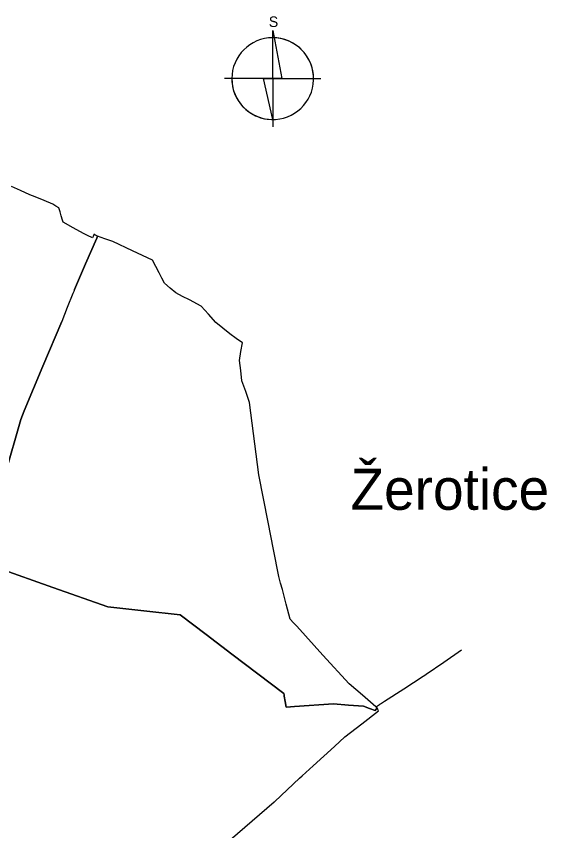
# Model space of a CAD drawing. Extents: x -637420 to -632365, y -1190340 to -1186955.
# Drawn here: x -633244 to -632365, y -1188691 to -1187341 of the extents above; entities that cross this region are included whole.
import ezdxf

# ---------------------------------------------------------------- set-up
doc = ezdxf.new("R2010")
doc.units = 0
for name, color, linetype in [('legenda', 7, 'Continuous'), ('Vrstva 1', 7, 'Continuous'), ('Vrstva 10', 7, 'Continuous'), ('Vrstva 11', 7, 'Continuous')]:
    doc.layers.add(name, color=color, linetype=linetype)

msp = doc.modelspace()

# ---------------------------------------------------------------- linework, layer by layer
at = {"layer": 'legenda'}
for p, q in [((-632819, -1187444), (-632819, -1187364)), ((-632819, -1187364), (-632803.9, -1187444)), ((-632819, -1187444), (-632819, -1187364)), ((-632819, -1187444), (-632819, -1187364)), ((-632819, -1187364), (-632803.9, -1187444)), ((-632819, -1187444), (-632819, -1187364)), ((-632819, -1187444), (-632899, -1187444)), ((-632819, -1187444), (-632899, -1187444)), ((-632819, -1187511.9), (-632834.1, -1187444)), ((-632834.1, -1187444), (-632819, -1187444)), ((-632819, -1187511.9), (-632834.1, -1187444)), ((-632834.1, -1187444), (-632819, -1187444)), ((-632819, -1187444), (-632819, -1187524)), ((-632803.9, -1187444), (-632819, -1187444)), ((-632819, -1187444), (-632819, -1187511.9)), ((-632819, -1187444), (-632739, -1187444)), ((-632819, -1187444), (-632819, -1187524)), ((-632803.9, -1187444), (-632819, -1187444)), ((-632819, -1187444), (-632819, -1187511.9)), ((-632819, -1187444), (-632739, -1187444))]:
    msp.add_line(p, q, dxfattribs=at)
for start_param, end_param in [(1.542214, 6.24931), (1.542214, 6.24931), (4.712403, 9.424778), (4.712403, 9.424778)]:
    msp.add_ellipse((-632819, -1187444), major_axis=(0, 67.8), ratio=0.999982, start_param=start_param, end_param=end_param, dxfattribs=at)
at = {"layer": 'Vrstva 1'}
for p, q in [((-632670, -1188466.5), (-632692.2, -1188447.3)), ((-632647.8, -1188485.7), (-632670, -1188466.5))]:
    msp.add_line(p, q, dxfattribs=at)
for points in [[(-633109.2, -1187705.1), (-633110, -1187706.8), (-633110.7, -1187708.6), (-633129.2, -1187751.1), (-633147.6, -1187793.6)], [(-632842.1, -1188100.7), (-632857.5, -1187980.9), (-632863.7, -1187963), (-632869.9, -1187945), (-632872, -1187928.1), (-632874.2, -1187911.3), (-632871.7, -1187896.7), (-632869.3, -1187882.2), (-632879.6, -1187874.7), (-632889.8, -1187867.2), (-632901.6, -1187857.6), (-632913.4, -1187848.1), (-632925.6, -1187834.6), (-632937.8, -1187821), (-632957.2, -1187811), (-632968.4, -1187805.1), (-632979.7, -1187799.2), (-632988.9, -1187791.3), (-632998.2, -1187783.4), (-633002.6, -1187774.7), (-633007.1, -1187766.1), (-633012.6, -1187755.5), (-633018.1, -1187744.9), (-633051.2, -1187729.6), (-633084.2, -1187714.3), (-633097.4, -1187709.4), (-633109.2, -1187705.1)], [(-633147.6, -1187793.6), (-633148.9, -1187797), (-633150.3, -1187800.4), (-633159.5, -1187823.6), (-633168.6, -1187846.9)], [(-633168.6, -1187846.9), (-633199.9, -1187920.9), (-633231.2, -1187994.9), (-633236.6, -1188009.2), (-633262.3, -1188099.9)], [(-632692.2, -1188447.3), (-632735.6, -1188399.7), (-632779, -1188352.1), (-632784.5, -1188346.1), (-632790, -1188340.1), (-632796.5, -1188315.6), (-632803, -1188291.1), (-632805.9, -1188280.3), (-632808.8, -1188269.6), (-632817.7, -1188224.5), (-632826.6, -1188179.4), (-632834.3, -1188140.1), (-632842.1, -1188100.7)], [(-633274, -1188255.4), (-633183.3, -1188287.6), (-633092.5, -1188319.8), (-633032.5, -1188326.3), (-632972.5, -1188332.8), (-632929.5, -1188365.4), (-632886.5, -1188398), (-632843.5, -1188430.7), (-632800.5, -1188463.3), (-632800.1, -1188465.5), (-632799.7, -1188467.7), (-632798.1, -1188476.9), (-632796.4, -1188486.1), (-632789.5, -1188485.6), (-632782.6, -1188485.1), (-632717.9, -1188480.8), (-632693.1, -1188482.7), (-632668.2, -1188484.6), (-632658.7, -1188488.1), (-632649.2, -1188491.6), (-632645.8, -1188487.4)], [(-632645.8, -1188487.4), (-632646.8, -1188486.6), (-632647.8, -1188485.7)]]:
    msp.add_lwpolyline(points, dxfattribs=at)
at = {"layer": 'Vrstva 10'}
for points in [[(-633117.3, -1187707), (-633117.8, -1187708.2), (-633125.9, -1187704.2), (-633132.8, -1187700.9), (-633149.7, -1187691.5), (-633166.6, -1187682.1), (-633167.1, -1187680.3), (-633167.6, -1187678.6), (-633169.6, -1187671.6), (-633171.6, -1187664.6), (-633172.5, -1187661.5), (-633173.5, -1187658.4), (-633178.4, -1187655.3), (-633183.3, -1187652.2), (-633197.9, -1187646.2), (-633212.6, -1187640.2), (-633217.1, -1187638.3), (-633221.7, -1187636.5), (-633236.9, -1187629.7), (-633252.2, -1187623)], [(-633109.2, -1187705.1), (-633111.9, -1187704.1), (-633113.7, -1187703), (-633115.5, -1187702), (-633116.2, -1187703.9), (-633116.9, -1187705.8), (-633117.3, -1187707)], [(-633147.6, -1187793.6), (-633129.2, -1187751.1), (-633110.7, -1187708.6), (-633110, -1187706.8), (-633109.2, -1187705.1)], [(-633147.6, -1187793.6), (-633148.9, -1187797), (-633150.3, -1187800.4), (-633159.5, -1187823.6), (-633168.6, -1187846.9)], [(-633262.3, -1188099.9), (-633236.6, -1188009.2), (-633231.2, -1187994.9), (-633199.9, -1187920.9), (-633168.6, -1187846.9)], [(-632889.7, -1188706), (-632853, -1188674.6), (-632816.3, -1188643.3), (-632815.5, -1188642.5), (-632795, -1188623.3), (-632774.4, -1188604.1), (-632770.1, -1188600.1), (-632752.1, -1188583.6), (-632734, -1188567.2), (-632716.6, -1188551.4), (-632699.2, -1188535.6), (-632671.3, -1188513.9), (-632643.3, -1188492.2), (-632644.6, -1188489.8), (-632645.8, -1188487.4), (-632649.2, -1188491.6), (-632658.7, -1188488.1), (-632668.2, -1188484.6), (-632693.1, -1188482.7), (-632717.9, -1188480.8), (-632782.6, -1188485.1), (-632789.5, -1188485.6), (-632796.4, -1188486.1), (-632798.1, -1188476.9), (-632799.7, -1188467.7), (-632800.1, -1188465.5), (-632800.5, -1188463.3), (-632843.5, -1188430.7), (-632886.5, -1188398), (-632929.5, -1188365.4), (-632972.5, -1188332.8), (-633032.5, -1188326.3), (-633092.5, -1188319.8), (-633183.3, -1188287.6), (-633274, -1188255.4)]]:
    msp.add_lwpolyline(points, dxfattribs=at)
at = {"layer": 'Vrstva 11'}
for p, q in [((-632601.5, -1188455.5), (-632569.3, -1188434.5)), ((-632670, -1188466.5), (-632692.2, -1188447.3)), ((-632647.8, -1188485.7), (-632670, -1188466.5))]:
    msp.add_line(p, q, dxfattribs=at)
for points in [[(-632842.1, -1188100.7), (-632857.5, -1187980.9), (-632863.7, -1187963), (-632869.9, -1187945), (-632872, -1187928.1), (-632874.2, -1187911.3), (-632871.7, -1187896.7), (-632869.3, -1187882.2), (-632879.6, -1187874.7), (-632889.8, -1187867.2), (-632901.6, -1187857.6), (-632913.4, -1187848.1), (-632925.6, -1187834.6), (-632937.8, -1187821), (-632957.2, -1187811), (-632968.4, -1187805.1), (-632979.7, -1187799.2), (-632988.9, -1187791.3), (-632998.2, -1187783.4), (-633002.6, -1187774.7), (-633007.1, -1187766.1), (-633012.6, -1187755.5), (-633018.1, -1187744.9), (-633051.2, -1187729.6), (-633084.2, -1187714.3), (-633097.4, -1187709.4), (-633109.2, -1187705.1)], [(-632692.2, -1188447.3), (-632735.6, -1188399.7), (-632779, -1188352.1), (-632784.5, -1188346.1), (-632790, -1188340.1), (-632796.5, -1188315.6), (-632803, -1188291.1), (-632805.9, -1188280.3), (-632808.8, -1188269.6), (-632817.7, -1188224.5), (-632826.6, -1188179.4), (-632834.3, -1188140.1), (-632842.1, -1188100.7)], [(-632569.3, -1188434.5), (-632567, -1188432.9), (-632564.6, -1188431.3), (-632535.2, -1188411.3), (-632505.7, -1188391.3)], [(-632642, -1188481.9), (-632641.1, -1188481.3), (-632640.3, -1188480.8), (-632636.9, -1188478.6), (-632633.6, -1188476.4), (-632601.5, -1188455.5)], [(-632645.8, -1188487.4), (-632646.8, -1188486.6), (-632647.8, -1188485.7), (-632647.3, -1188485.4), (-632646.7, -1188485), (-632646, -1188484.5), (-632645.3, -1188484.1)], [(-632645.3, -1188484.1), (-632643.7, -1188483), (-632642, -1188481.9)]]:
    msp.add_lwpolyline(points, dxfattribs=at)

# ---------------------------------------------------------------- texts
at = {"layer": 'legenda'}
for s, height, p in [('S', 17.5, (-632825.4, -1187358.4)), ('S', 17.5, (-632825.4, -1187358.4)), ('Žerotice', 68.2, (-632690, -1188158.9))]:
    msp.add_text(s, height=height, dxfattribs=at).set_placement(p)

doc.saveas('drawing.dxf')
